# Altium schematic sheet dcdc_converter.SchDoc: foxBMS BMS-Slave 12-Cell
size A3; DocumentNumber: 15; SheetNumber: 15; SheetTotal: 15; AUTHOR: Fraunhofer IISB foxBMS Team; SheetDescription: DC/DC Converter
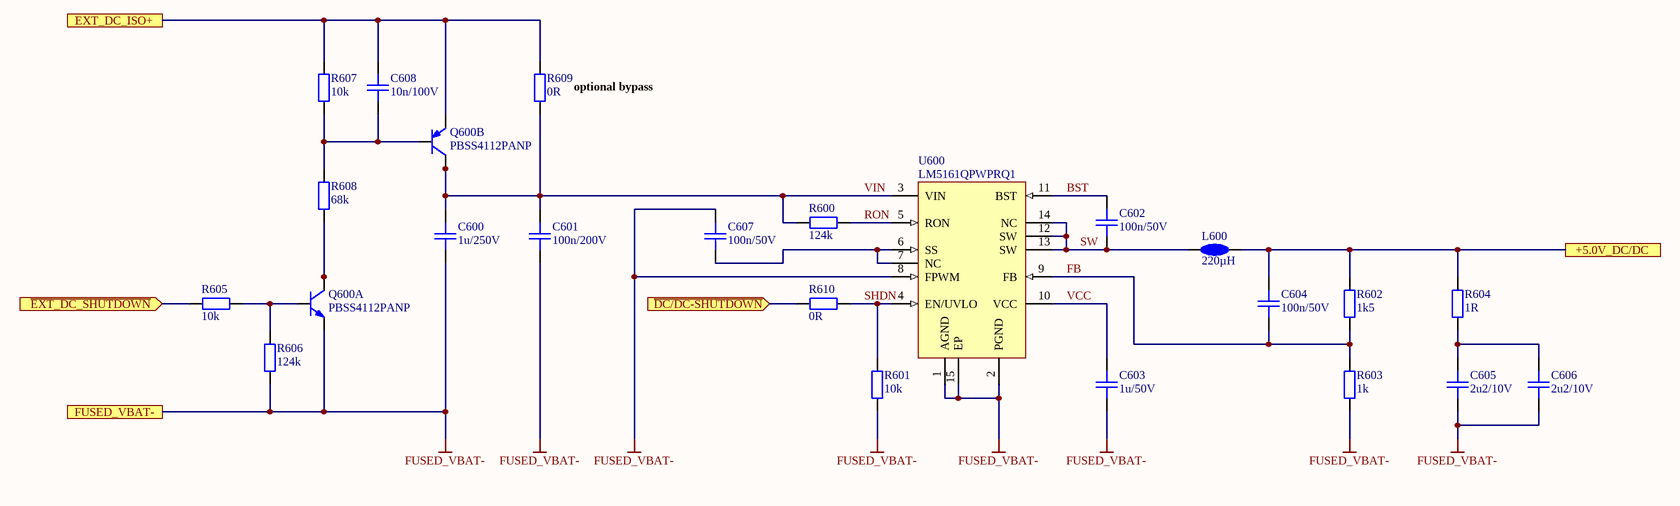
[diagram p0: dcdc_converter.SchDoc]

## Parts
C600  1u/250V  [CAPC4532X16N]
C601  100n/200V  [CAPC3216X18N]
C602  100n/50V  [CAPC1608X08N]
C603  1u/50V  [CAPC2012X14N]
C604  100n/50V  [CAPC1608X08N]
C605  2u2/10V  [CAPC2012X14N]
C606  2u2/10V  [CAPC2012X14N]
C607  100n/50V  [CAPC1608X08N]
C608  10n/100V  [CAPC1608X08N]
L600  220µH  [TYS6045221M-10]
Q600  PBSS4112PANP  [PBSS4112PANP]  (parts A,B of 2)
R600  124k  [RESC1608X05N]
R601  10k  [RESC1608X05N]
R602  1k5  [RESC1608X05N]
R603  1k  [RESC1608X05N]
R604  1R  [RESC2012X05N]
R605  10k  [RESC1608X05N]
R606  124k  [RESC1608X05N]
R607  10k  [RESC1608X05N]
R608  68k  [RESC1608X05N]
R609  0R  [RESC1608X05N]
R610  0R  [RESC1608X05N]
U600  LM5161QPWPRQ1  [PWP0014A]

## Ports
+5.0V_DC/DC, EXT_DC_ISO+, FUSED_VBAT-, ~{DC/DC-SHUTDOWN} (in), ~{EXT_DC_SHUTDOWN} (in)

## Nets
FUSED_VBAT-: C600.1 C601.1 C603.1 C605.1 C606.1 C607.2 Q600.1(E) R601.2 R603.2 R606.1 U600.1(AGND) U600.2(PGND) U600.8(FPWM) U600.15(EP) ; port FUSED_VBAT-
+5.0V_DC/DC: C604.2 L600.2 R602.1 R604.1 ; port +5.0V_DC/DC
~{DC/DC-SHUTDOWN}: R610.2 ; port ~{DC/DC-SHUTDOWN}
~{EXT_DC_SHUTDOWN}: R605.1 ; port ~{EXT_DC_SHUTDOWN}
BST: C602.2 U600.11(BST)
EXT_DC_ISO+: C608.1 Q600.4(E) R607.2 R609.2 ; port EXT_DC_ISO+
FB: C604.1 R602.2 R603.1 U600.9(FB)
RON: R600.1 U600.5(RON)
SHDN: R601.1 R610.1 U600.4(EN/UVLO)
SW: C602.1 L600.1 U600.12(SW) U600.13(SW) U600.14(NC)
VCC: C603.2 U600.10(VCC)
VIN: C600.2 C601.2 Q600.3(C) Q600.8(C) R600.2 R609.1 U600.3(VIN)
NetC605_2: C605.2 C606.2 R604.2
NetC607_1: C607.1 U600.6(SS) U600.7(NC)
NetC608_2: C608.2 Q600.5(B) R607.1 R608.2
NetQ600_2: Q600.2(B) R605.2 R606.2
NetQ600_6: Q600.6(C) Q600.7(C) R608.1

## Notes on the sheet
- (near R609) optional bypass

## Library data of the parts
C600 = gen_C_ceramic_1u_250V_X7R_1812: MLCC; Capacitance: 1u; Rated Voltage: 250V; Dielectric: X7T; Case EIA: 1812; Case Metric: 4532; Automotive Qualified: True
C601 = gen_C_ceramic_100n_200V_X7R_1206: MLCC; Capacitance: 100n; Rated Voltage: 200V; Dielectric: X7R; Case EIA: 1206; Case Metric: 3216; Automotive Qualified: True
C602 C604 C607 = gen_C_ceramic_100n_50V_X7R_0603: MLCC; Capacitance: 100n; Rated Voltage: 50V; Dielectric: X7R; Case EIA: 0603; Case Metric: 1608; PnP Package: C_0603_10; PnP Value: 100n/50V/X7R; PnP equipped: x; Automotive Qualified: True
C603 = gen_C_ceramic_1u_50V_X7R_0805: MLCC; Capacitance: 1u; Rated Voltage: 50V; Dielectric: X7R; Case EIA: 0805; Case Metric: 2012; Automotive Qualified: True; Tolerance: ± 10%; AVT Set: x
C605 C606 = gen_C_ceramic_2u2_10V_X7R_0805: MLCC; Capacitance: 2u2; Rated Voltage: 10V; Dielectric: X7R; Case EIA: 0805; Case Metric: 2012; Automotive Qualified: True
C608 = gen_C_ceramic_10n_100V_X7R_0603: MLCC; Capacitance: 10n; Rated Voltage: 100V; Dielectric: X7R; Case EIA: 0603; Case Metric: 1608; Automotive Qualified: True
L600 = TYS6045221M-10: Power Inductor; Manufacturer: Laird-Signal Integrity Products; Rated Current: 590mA; Saturation Current: 700mA; Automotive Qualified: True
Q600 = PBSS4112PANP: Dual NPN/PNP Transistor; Part Name: DUAL PNP/NPN; Manufacturer: Nexperia; Maximum Drain-Source Voltage: 120V; Maximum Continous Drain Current (25°C): 1A; Automotive Qualified: True
R600 R606 = gen_R_124k_0603: SMD Resistor 124k 0603; Tolerance: 1%; Power: 0.1W; Case EIA: 0603; Case Metric: 1608; Maximum Working Voltage: 75V; PnP Package: R_0603; Automotive Qualified: True
R601 R605 R607 = gen_R_10k_0603: SMD Resistor 10k 0603; Tolerance: 1%; Power: 0.1W; Case EIA: 0603; Case Metric: 1608; Maximum Working Voltage: 75V; PnP Package: R_0603; Automotive Qualified: True
R602 = gen_R_1k5_0603: SMD Resistor 1k5 0603; Tolerance: 1%; Power: 0.1W; Case EIA: 0603; Case Metric: 1608; Maximum Working Voltage: 75V; PnP Package: R_0603; Automotive Qualified: True
R603 = gen_R_1k_0603: SMD Resistor 1k 0603; Tolerance: 1%; Power: 0.1W; Case EIA: 0603; Case Metric: 1608; Maximum Working Voltage: 75V; PnP Package: R_0603; Automotive Qualified: True; PnP equipped: x
R604 = gen_R_1R_0805: SMD Resistor 1R 0805; Tolerance: 1%; Power: 0.125W; Case EIA: 0805; Case Metric: 2012; Maximum Working Voltage: 150V; PnP Package: R_0805; Automotive Qualified: True
R608 = gen_R_68k_0603: SMD Resistor 68k 0603; Tolerance: 1%; Power: 0.1W; Case EIA: 0603; Case Metric: 1608; Maximum Working Voltage: 75V; PnP Package: R_0603; Automotive Qualified: False
R609 R610 = gen_R_0R_0603: SMD Resistor 0R 0603; Power: 0.1W; Case EIA: 0603; Case Metric: 1608; Maximum Working Voltage: 75V; PnP Package: R_0603; Automotive Qualified: True
U600 = LM5161QPWPRQ1: Automotive DC/DC buck converter; Manufacturer: Texas Instruments; PnP Package: HTSSOP-14; Automotive Qualified: True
